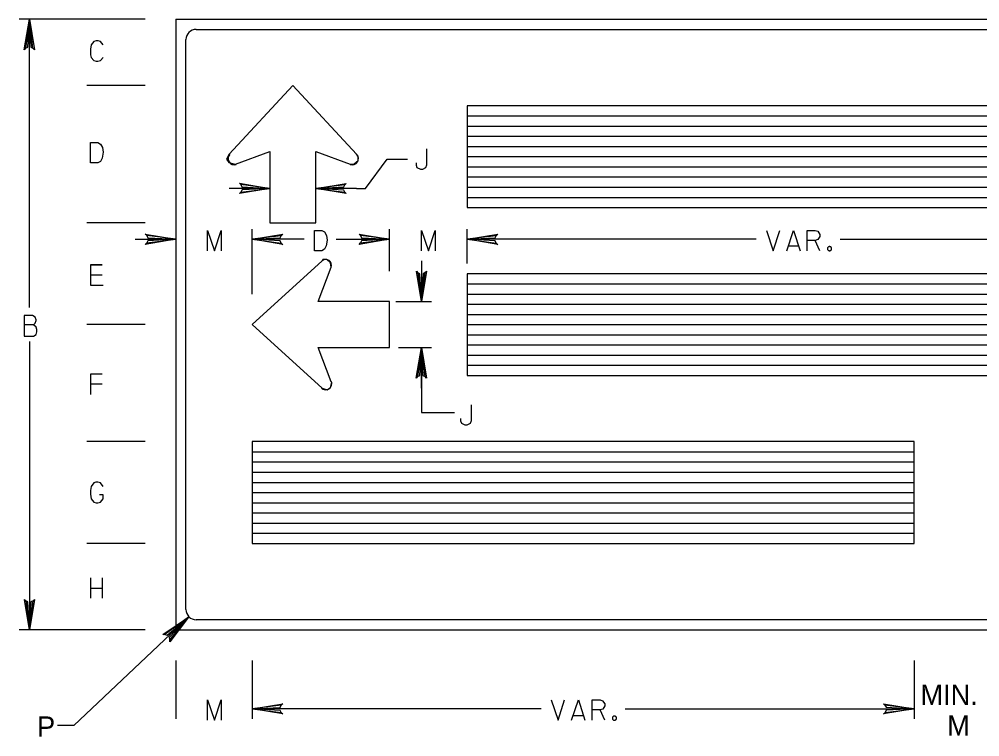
# Model space of a CAD drawing. Extents: x 0.011 to 0.188, y 0.004 to 0.261.
# Drawn here: x 0.0335 to 0.1286, y 0.1204 to 0.1915 of the extents above; entities that cross this region are included whole.
import ezdxf

# ---------------------------------------------------------------- set-up
doc = ezdxf.new("R2010")
doc.units = 0
for name, color, linetype in [('1', 7, 'Continuous'), ('2', 7, 'Continuous'), ('3', 7, 'Continuous')]:
    doc.layers.add(name, color=color, linetype=linetype)

# ---------------------------------------------------------------- blocks, each defined once
blk = doc.blocks.new('RARROW')
at = {"layer": '3'}
for p, q in [((-2.156, 0.285), (-2.2665, 0.384625)), ((-2.2665, 0.384625), (0, 0)), ((0, 0), (-2.2665, -0.379125)), ((-2.156, 0.285), (-2.075625, 0.12075)), ((0, 0), (-2.156, 0.285)), ((-2.14975, -0.2705), (0, 0)), ((-2.075625, 0.12075), (0, 0)), ((0, 0), (-2.074, -0.108)), ((-2.2665, -0.379125), (-2.14975, -0.2705)), ((-2.074, -0.108), (-2.14975, -0.2705))]:
    blk.add_line(p, q, dxfattribs=at)

msp = doc.modelspace()

# ---------------------------------------------------------------- linework, layer by layer
at = {"layer": '1'}
for points in [[(0.054923, 0.177146), (0.058325, 0.178406), (0.058325, 0.17135), (0.062861, 0.17135), (0.062861, 0.178406), (0.066263, 0.177146), (0.066661, 0.177193), (0.067041, 0.17751), (0.067041, 0.177952), (0.066893, 0.178154), (0.060593, 0.184958), (0.054293, 0.178154), (0.054009, 0.177636), (0.054262, 0.17732)], [(0.064373, 0.16694), (0.064321, 0.167388), (0.063941, 0.167704), (0.063562, 0.167704), (0.063491, 0.16757), (0.056561, 0.16127), (0.063491, 0.15497), (0.064004, 0.154799), (0.064321, 0.155052), (0.064447, 0.155558), (0.064373, 0.1556), (0.063113, 0.159002), (0.070169, 0.159002), (0.070169, 0.163538), (0.063113, 0.163538)]]:
    msp.add_lwpolyline(points, close=True, dxfattribs=at)
at = {"layer": '2'}
for p, q in [((0.049001, 0.19151), (0.049001, 0.13103)), ((0.049001, 0.19151), (0.169961, 0.19151)), ((0.049001, 0.13103), (0.169961, 0.13103))]:
    msp.add_line(p, q, dxfattribs=at)
at = {"layer": '3'}
for p, q in [((0.042953, 0.19151), (0.033503, 0.19151)), ((0.034511, 0.16295), (0.034511, 0.19151)), ((0.045977, 0.19151), (0.040181, 0.19151)), ((0.051017, 0.190502), (0.167567, 0.190502)), ((0.050009, 0.133046), (0.050009, 0.189494)), ((0.045977, 0.184958), (0.040181, 0.184958)), ((0.060593, 0.184958), (0.054293, 0.178154)), ((0.066893, 0.178154), (0.060593, 0.184958)), ((0.143375, 0.182942), (0.077855, 0.182942)), ((0.077855, 0.182942), (0.077855, 0.172862)), ((0.077855, 0.181934), (0.143375, 0.181934)), ((0.077855, 0.180926), (0.143375, 0.180926)), ((0.077855, 0.179918), (0.143375, 0.179918)), ((0.077855, 0.17891), (0.143375, 0.17891)), ((0.054923, 0.177146), (0.058325, 0.178406)), ((0.058325, 0.178406), (0.058325, 0.17135)), ((0.062861, 0.17135), (0.062861, 0.178406)), ((0.062861, 0.178406), (0.066263, 0.177146)), ((0.077855, 0.177902), (0.143375, 0.177902)), ((0.067775, 0.174752), (0.069917, 0.17765)), ((0.069917, 0.17765), (0.071933, 0.17765)), ((0.077855, 0.176894), (0.143375, 0.176894)), ((0.055449, 0.175129), (0.055301, 0.17526)), ((0.055301, 0.17526), (0.058325, 0.174752)), ((0.055449, 0.175129), (0.055556, 0.174912)), ((0.058325, 0.174752), (0.055449, 0.175129)), ((0.062861, 0.174752), (0.065885, 0.175253)), ((0.06573, 0.175109), (0.062861, 0.174752)), ((0.065629, 0.174895), (0.06573, 0.175109)), ((0.065885, 0.175253), (0.06573, 0.175109)), ((0.077855, 0.175886), (0.143375, 0.175886)), ((0.058325, 0.174752), (0.054293, 0.174752)), ((0.058325, 0.174752), (0.055301, 0.174252)), ((0.055301, 0.174252), (0.055457, 0.174395)), ((0.055457, 0.174395), (0.058325, 0.174752)), ((0.055558, 0.17461), (0.055457, 0.174395)), ((0.055556, 0.174912), (0.058325, 0.174752)), ((0.058325, 0.174752), (0.055558, 0.17461)), ((0.056309, 0.174752), (0.058325, 0.174752)), ((0.062861, 0.174752), (0.065629, 0.174895)), ((0.066893, 0.174752), (0.062861, 0.174752)), ((0.065631, 0.174593), (0.062861, 0.174752)), ((0.062861, 0.174752), (0.065738, 0.174376)), ((0.065885, 0.174245), (0.062861, 0.174752)), ((0.065738, 0.174376), (0.065631, 0.174593)), ((0.065738, 0.174376), (0.065885, 0.174245)), ((0.066893, 0.174752), (0.067775, 0.174752)), ((0.077855, 0.174878), (0.143375, 0.174878)), ((0.077855, 0.17387), (0.143375, 0.17387)), ((0.077855, 0.172862), (0.143375, 0.172862)), ((0.045977, 0.17135), (0.040181, 0.17135)), ((0.058325, 0.17135), (0.062861, 0.17135)), ((0.046125, 0.170089), (0.045977, 0.17022)), ((0.045977, 0.17022), (0.049001, 0.169712)), ((0.056561, 0.164294), (0.056561, 0.17072)), ((0.056561, 0.169712), (0.059585, 0.170213)), ((0.059585, 0.170213), (0.05943, 0.170069)), ((0.067293, 0.170089), (0.067145, 0.17022)), ((0.067145, 0.17022), (0.070169, 0.169712)), ((0.070169, 0.166562), (0.070169, 0.17072)), ((0.077855, 0.167318), (0.077855, 0.17072)), ((0.077855, 0.169712), (0.080879, 0.170213)), ((0.080879, 0.170213), (0.080724, 0.170069)), ((0.044969, 0.169712), (0.049001, 0.169712)), ((0.049001, 0.169712), (0.045977, 0.169212)), ((0.045977, 0.169212), (0.046133, 0.169355)), ((0.046125, 0.170089), (0.046232, 0.169872)), ((0.049001, 0.169712), (0.046125, 0.170089)), ((0.046133, 0.169355), (0.049001, 0.169712)), ((0.046234, 0.16957), (0.046133, 0.169355)), ((0.046232, 0.169872), (0.049001, 0.169712)), ((0.049001, 0.169712), (0.046234, 0.16957)), ((0.05943, 0.170069), (0.056561, 0.169712)), ((0.056561, 0.169712), (0.059329, 0.169855)), ((0.060593, 0.169712), (0.056561, 0.169712)), ((0.061727, 0.169712), (0.056561, 0.169712)), ((0.059331, 0.169553), (0.056561, 0.169712)), ((0.056561, 0.169712), (0.059438, 0.169336)), ((0.059585, 0.169205), (0.056561, 0.169712)), ((0.059329, 0.169855), (0.05943, 0.170069)), ((0.059438, 0.169336), (0.059331, 0.169553)), ((0.059438, 0.169336), (0.059585, 0.169205)), ((0.064877, 0.169712), (0.070169, 0.169712)), ((0.066137, 0.169712), (0.070169, 0.169712)), ((0.070169, 0.169712), (0.067145, 0.169212)), ((0.067145, 0.169212), (0.067301, 0.169355)), ((0.067293, 0.170089), (0.0674, 0.169872)), ((0.070169, 0.169712), (0.067293, 0.170089)), ((0.067301, 0.169355), (0.070169, 0.169712)), ((0.067402, 0.16957), (0.067301, 0.169355)), ((0.0674, 0.169872), (0.070169, 0.169712)), ((0.070169, 0.169712), (0.067402, 0.16957)), ((0.080724, 0.170069), (0.077855, 0.169712)), ((0.077855, 0.169712), (0.080623, 0.169855)), ((0.081887, 0.169712), (0.077855, 0.169712)), ((0.106457, 0.169712), (0.077855, 0.169712)), ((0.080625, 0.169553), (0.077855, 0.169712)), ((0.077855, 0.169712), (0.080732, 0.169336)), ((0.080879, 0.169205), (0.077855, 0.169712)), ((0.080623, 0.169855), (0.080724, 0.170069)), ((0.080732, 0.169336), (0.080625, 0.169553)), ((0.080732, 0.169336), (0.080879, 0.169205)), ((0.114773, 0.169712), (0.143375, 0.169712)), ((0.063491, 0.16757), (0.056561, 0.16127)), ((0.073319, 0.16757), (0.073319, 0.163538)), ((0.063113, 0.163538), (0.064373, 0.16694)), ((0.143375, 0.16631), (0.077855, 0.16631)), ((0.077855, 0.16631), (0.077855, 0.15623)), ((0.077855, 0.165302), (0.143375, 0.165302)), ((0.077855, 0.164294), (0.143375, 0.164294)), ((0.070169, 0.163538), (0.063113, 0.163538)), ((0.070169, 0.159002), (0.070169, 0.163538)), ((0.070799, 0.163538), (0.074327, 0.163538)), ((0.077855, 0.163286), (0.143375, 0.163286)), ((0.077855, 0.162278), (0.143375, 0.162278)), ((0.045977, 0.16127), (0.040181, 0.16127)), ((0.056561, 0.16127), (0.063491, 0.15497)), ((0.077855, 0.16127), (0.143375, 0.16127)), ((0.077855, 0.160262), (0.143375, 0.160262)), ((0.034511, 0.15959), (0.034511, 0.13103)), ((0.064373, 0.1556), (0.063113, 0.159002)), ((0.063113, 0.159002), (0.070169, 0.159002)), ((0.071051, 0.159002), (0.074327, 0.159002)), ((0.073319, 0.159002), (0.073319, 0.152576)), ((0.073319, 0.15497), (0.073319, 0.159002)), ((0.077855, 0.159254), (0.143375, 0.159254)), ((0.077855, 0.158246), (0.143375, 0.158246)), ((0.077855, 0.157238), (0.143375, 0.157238)), ((0.077855, 0.15623), (0.143375, 0.15623)), ((0.073319, 0.152576), (0.076595, 0.152576)), ((0.045977, 0.149678), (0.040181, 0.149678)), ((0.122081, 0.149678), (0.056561, 0.149678)), ((0.056561, 0.149678), (0.056561, 0.139598)), ((0.122081, 0.139598), (0.122081, 0.149678)), ((0.056561, 0.14867), (0.122081, 0.14867)), ((0.056561, 0.147662), (0.122081, 0.147662)), ((0.056561, 0.146654), (0.122081, 0.146654)), ((0.056561, 0.145646), (0.122081, 0.145646)), ((0.056561, 0.144638), (0.122081, 0.144638)), ((0.056561, 0.14363), (0.122081, 0.14363)), ((0.056561, 0.142622), (0.122081, 0.142622)), ((0.056561, 0.141614), (0.122081, 0.141614)), ((0.056561, 0.140606), (0.122081, 0.140606)), ((0.045977, 0.139598), (0.040181, 0.139598)), ((0.056561, 0.139598), (0.122081, 0.139598)), ((0.050261, 0.13229), (0.038921, 0.12158)), ((0.167567, 0.132038), (0.051017, 0.132038)), ((0.042953, 0.13103), (0.033503, 0.13103)), ((0.045977, 0.13103), (0.040181, 0.13103)), ((0.049001, 0.128006), (0.049001, 0.12221)), ((0.056561, 0.128006), (0.056561, 0.12221)), ((0.122081, 0.128006), (0.122081, 0.12221)), ((0.056561, 0.123218), (0.059585, 0.123719)), ((0.059585, 0.123719), (0.05943, 0.123575)), ((0.119205, 0.123595), (0.119057, 0.123726)), ((0.119057, 0.123726), (0.122081, 0.123218)), ((0.05943, 0.123575), (0.056561, 0.123218)), ((0.056561, 0.123218), (0.059329, 0.123361)), ((0.060593, 0.123218), (0.056561, 0.123218)), ((0.085163, 0.123218), (0.056561, 0.123218)), ((0.059331, 0.123059), (0.056561, 0.123218)), ((0.056561, 0.123218), (0.059438, 0.122842)), ((0.059585, 0.122711), (0.056561, 0.123218)), ((0.059329, 0.123361), (0.05943, 0.123575)), ((0.059438, 0.122842), (0.059331, 0.123059)), ((0.059438, 0.122842), (0.059585, 0.122711)), ((0.093479, 0.123218), (0.122081, 0.123218)), ((0.118049, 0.123218), (0.122081, 0.123218)), ((0.122081, 0.123218), (0.119057, 0.122718)), ((0.119057, 0.122718), (0.119213, 0.122861)), ((0.119205, 0.123595), (0.119312, 0.123378)), ((0.122081, 0.123218), (0.119205, 0.123595)), ((0.119213, 0.122861), (0.122081, 0.123218)), ((0.119314, 0.123076), (0.119213, 0.122861)), ((0.119312, 0.123378), (0.122081, 0.123218)), ((0.122081, 0.123218), (0.119314, 0.123076)), ((0.038921, 0.12158), (0.037283, 0.12158))]:
    msp.add_line(p, q, dxfattribs=at)
for points in [[(0.041814, 0.188972), (0.04156, 0.189305), (0.041306, 0.189369), (0.041131, 0.189369), (0.040893, 0.189305), (0.040623, 0.188972), (0.040559, 0.188527), (0.040559, 0.188289), (0.040559, 0.18813), (0.040575, 0.187987), (0.040623, 0.187733), (0.040893, 0.187416), (0.041131, 0.187352), (0.041274, 0.187352), (0.041544, 0.187416), (0.041814, 0.187733)], [(0.040559, 0.179289), (0.04129, 0.179289), (0.04156, 0.179146), (0.041734, 0.178796), (0.041814, 0.178336), (0.041718, 0.177765), (0.041544, 0.177415), (0.04129, 0.177272), (0.040559, 0.177272), (0.040559, 0.179289)], [(0.073816, 0.178659), (0.073816, 0.177055), (0.07372, 0.176785), (0.073419, 0.176642), (0.073244, 0.176642), (0.072895, 0.176785), (0.072815, 0.177039), (0.072815, 0.177293)], [(0.052151, 0.168578), (0.052151, 0.170595), (0.05285, 0.168578), (0.053501, 0.170595), (0.053501, 0.168578)], [(0.062735, 0.170595), (0.063466, 0.170595), (0.063736, 0.170452), (0.06391, 0.170102), (0.06399, 0.169642), (0.063894, 0.169071), (0.06372, 0.168721), (0.063466, 0.168578), (0.062735, 0.168578), (0.062735, 0.170595)], [(0.073319, 0.168578), (0.073319, 0.170595), (0.074018, 0.168578), (0.074669, 0.170595), (0.074669, 0.168578)], [(0.107465, 0.170595), (0.108132, 0.168578), (0.108783, 0.170595)], [(0.109482, 0.168578), (0.110148, 0.170595), (0.110799, 0.168578)], [(0.111498, 0.168578), (0.111498, 0.170595), (0.112308, 0.170595), (0.112546, 0.170515), (0.112752, 0.170198), (0.112752, 0.170007), (0.112562, 0.16969), (0.112308, 0.16961), (0.111498, 0.16961)], [(0.112752, 0.168578), (0.112292, 0.16961)], [(0.10964, 0.169055), (0.110641, 0.169055)], [(0.113927, 0.168785), (0.113926, 0.168806), (0.113922, 0.168828), (0.113917, 0.168848), (0.113909, 0.168869), (0.113899, 0.168888), (0.113887, 0.168906), (0.113874, 0.168923), (0.113859, 0.168938), (0.113842, 0.168952), (0.113824, 0.168963), (0.113804, 0.168973), (0.113784, 0.168981), (0.113763, 0.168987), (0.113742, 0.16899), (0.11372, 0.168991), (0.113699, 0.16899), (0.113678, 0.168987), (0.113657, 0.168981), (0.113637, 0.168973), (0.113617, 0.168963), (0.113599, 0.168952), (0.113582, 0.168938), (0.113567, 0.168923), (0.113554, 0.168906), (0.113542, 0.168888), (0.113532, 0.168869), (0.113524, 0.168848), (0.113519, 0.168828), (0.113515, 0.168806), (0.113514, 0.168785), (0.113515, 0.168763), (0.113519, 0.168742), (0.113524, 0.168721), (0.113532, 0.168701), (0.113542, 0.168682), (0.113554, 0.168663), (0.113567, 0.168647), (0.113582, 0.168631), (0.113599, 0.168618), (0.113617, 0.168606), (0.113637, 0.168596), (0.113657, 0.168589), (0.113678, 0.168583), (0.113699, 0.168579), (0.11372, 0.168578), (0.113742, 0.168579), (0.113763, 0.168583), (0.113784, 0.168589), (0.113804, 0.168596), (0.113824, 0.168606), (0.113842, 0.168618), (0.113859, 0.168631), (0.113874, 0.168647), (0.113887, 0.168663), (0.113899, 0.168682), (0.113909, 0.168701), (0.113917, 0.168721), (0.113922, 0.168742), (0.113926, 0.168763), (0.113927, 0.168785)], [(0.041718, 0.167193), (0.040559, 0.167193), (0.040559, 0.165176), (0.041798, 0.165176)], [(0.040559, 0.167193), (0.041718, 0.167193)], [(0.040559, 0.166192), (0.041718, 0.166192)], [(0.040559, 0.166192), (0.041718, 0.166192)], [(0.034912, 0.161232), (0.035087, 0.161422), (0.035166, 0.16166), (0.035166, 0.16174), (0.035087, 0.16201), (0.034817, 0.162153), (0.034007, 0.162153), (0.034007, 0.160136), (0.034912, 0.160136), (0.035166, 0.160279), (0.035262, 0.160549), (0.035262, 0.160787), (0.035166, 0.161025), (0.034912, 0.161232), (0.034007, 0.161232)], [(0.041718, 0.156357), (0.040559, 0.156357), (0.040559, 0.15434)], [(0.040559, 0.155372), (0.040559, 0.155372)], [(0.041702, 0.155372), (0.040559, 0.155372)], [(0.078226, 0.153333), (0.078226, 0.151729), (0.07813, 0.151459), (0.077829, 0.151316), (0.077654, 0.151316), (0.077305, 0.151459), (0.077225, 0.151713), (0.077225, 0.151967)], [(0.041814, 0.14525), (0.041544, 0.145583), (0.04129, 0.145647), (0.041099, 0.145647), (0.040893, 0.145583), (0.040623, 0.14525), (0.040559, 0.144821), (0.040559, 0.144488), (0.040639, 0.144011), (0.040877, 0.143694), (0.041115, 0.14363), (0.04129, 0.14363), (0.041544, 0.143694), (0.041814, 0.144027), (0.041814, 0.144424), (0.041464, 0.144424)], [(0.040559, 0.136197), (0.040559, 0.13418)], [(0.041702, 0.136197), (0.041702, 0.13418)], [(0.040559, 0.135181), (0.041702, 0.135181)], [(0.052151, 0.122084), (0.052151, 0.124101), (0.05285, 0.122084), (0.053501, 0.124101), (0.053501, 0.122084)], [(0.086171, 0.124101), (0.086838, 0.122084), (0.087489, 0.124101)], [(0.088188, 0.122084), (0.088854, 0.124101), (0.089505, 0.122084)], [(0.090204, 0.122084), (0.090204, 0.124101), (0.091014, 0.124101), (0.091252, 0.124021), (0.091458, 0.123704), (0.091458, 0.123513), (0.091268, 0.123196), (0.091014, 0.123116), (0.090204, 0.123116)], [(0.091458, 0.122084), (0.090998, 0.123116)], [(0.088346, 0.122561), (0.089347, 0.122561)], [(0.092633, 0.122291), (0.092632, 0.122312), (0.092628, 0.122334), (0.092623, 0.122354), (0.092615, 0.122375), (0.092605, 0.122394), (0.092593, 0.122412), (0.09258, 0.122429), (0.092565, 0.122444), (0.092548, 0.122458), (0.09253, 0.122469), (0.09251, 0.122479), (0.09249, 0.122487), (0.092469, 0.122493), (0.092448, 0.122496), (0.092426, 0.122497), (0.092405, 0.122496), (0.092384, 0.122493), (0.092363, 0.122487), (0.092343, 0.122479), (0.092323, 0.122469), (0.092305, 0.122458), (0.092288, 0.122444), (0.092273, 0.122429), (0.09226, 0.122412), (0.092248, 0.122394), (0.092238, 0.122375), (0.09223, 0.122354), (0.092225, 0.122334), (0.092221, 0.122312), (0.09222, 0.122291), (0.092221, 0.122269), (0.092225, 0.122248), (0.09223, 0.122227), (0.092238, 0.122207), (0.092248, 0.122188), (0.09226, 0.122169), (0.092273, 0.122153), (0.092288, 0.122137), (0.092305, 0.122124), (0.092323, 0.122112), (0.092343, 0.122102), (0.092363, 0.122095), (0.092384, 0.122089), (0.092405, 0.122085), (0.092426, 0.122084), (0.092448, 0.122085), (0.092469, 0.122089), (0.09249, 0.122095), (0.09251, 0.122102), (0.09253, 0.122112), (0.092548, 0.122124), (0.092565, 0.122137), (0.09258, 0.122153), (0.092593, 0.122169), (0.092605, 0.122188), (0.092615, 0.122207), (0.092623, 0.122227), (0.092628, 0.122248), (0.092632, 0.122269), (0.092633, 0.122291)]]:
    msp.add_lwpolyline(points, dxfattribs=at)
for centre, radius, start, end in [((0.051017, 0.189494), 0.001008, 90, 180), ((0.054792, 0.177712), 0.00061, 137.1211, 289.17901), ((0.066478, 0.177712), 0.00061, 250.82099, 42.8789), ((0.063854, 0.167146), 0.000558, 338.43337, 130.49128), ((0.063847, 0.155425), 0.00061, 227.1211, 19.17901), ((0.051017, 0.133046), 0.001008, 180, 270)]:
    msp.add_arc(centre, radius, start, end, dxfattribs=at)

# ---------------------------------------------------------------- block references
at = {"layer": '3', "yscale": 0.0013198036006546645}
for p, xscale, rotation in [((0.034511, 0.19151), 0.0013342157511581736, 90), ((0.073319, 0.163538), 0.0013342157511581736, -90), ((0.073319, 0.159002), 0.0013342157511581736, 90), ((0.034511, 0.13103), 0.0013342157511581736, -90), ((0.050261, 0.13229), 0.0013342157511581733, 43.36342295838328)]:
    msp.add_blockref('RARROW', p, dxfattribs=dict(at, xscale=xscale, rotation=rotation))

# ---------------------------------------------------------------- texts
at = {"layer": '3'}
for s, height, p in [('MIN.', 0.0020163, (0.122711, 0.123596)), ('P', 0.002016, (0.035267, 0.120446)), ('M', 0.002016, (0.125357, 0.120572))]:
    msp.add_text(s, height=height, dxfattribs=at).set_placement(p)

doc.saveas('drawing.dxf')
